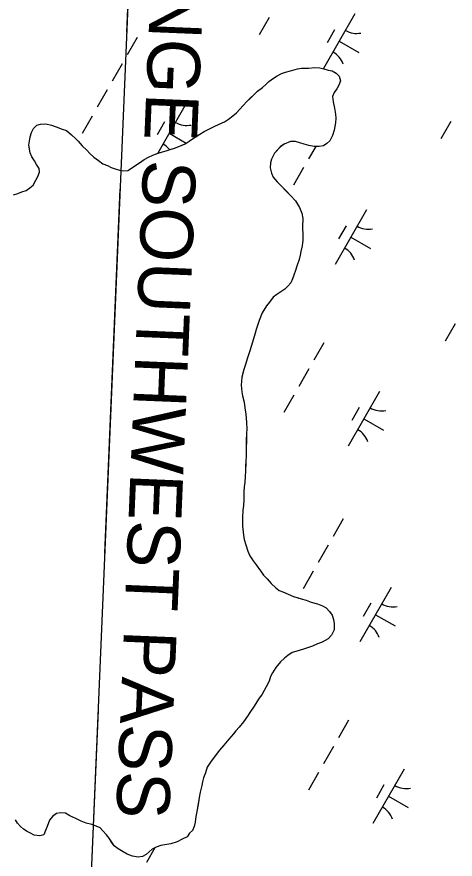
# Model space of a CAD drawing. Extents: x 3930721 to 3950824, y 220441 to 242861.
# Drawn here: x 3943622 to 3943971, y 232859 to 233530 of the extents above; entities that cross this region are included whole.
import ezdxf

# ---------------------------------------------------------------- set-up
doc = ezdxf.new("R2010")
doc.units = 0
for name, color, linetype in [('V-RIVR-RANG', 7, 'Continuous'), ('V-RIVR-RANG-IDEN', 7, 'Continuous'), ('V-TOPO-MINR', 7, 'Continuous'), ('V-TOPO-SHOR', 7, 'Continuous'), ('V-WETL-SWMP', 7, 'Continuous')]:
    doc.layers.add(name, color=color, linetype=linetype)

msp = doc.modelspace()

# ---------------------------------------------------------------- linework, layer by layer
at = {"layer": 'V-RIVR-RANG'}
for points in [[(3943765.57, 234844.6), (3943658.87, 232314.65)], [(3943765.57, 234844.6), (3943658.87, 232314.65)], [(3943721.82, 233807.23), (3943709.6, 233517.49)], [(3943704.33, 233392.6), (3943692.11, 233102.86)], [(3943686.84, 232977.97), (3943674.62, 232688.23)]]:
    msp.add_lwpolyline(points, dxfattribs=at)
at = {"layer": 'V-TOPO-MINR'}
msp.add_lwpolyline([(3943765.57, 234844.6), (3943658.87, 232314.65)], dxfattribs=at)
at = {"layer": 'V-TOPO-SHOR'}
for points in [[(3943631.81, 233427.64), (3943632.4, 233430.67), (3943633, 233434.26), (3943633.88, 233437.56), (3943635.58, 233440.86), (3943638.1, 233443.59), (3943641.15, 233444.38), (3943645.3, 233444.6), (3943649.98, 233443.43), (3943653.56, 233442.28), (3943658.24, 233440.28), (3943661.81, 233439.13), (3943665.64, 233435.76), (3943668.92, 233432.95), (3943671.1, 233430.71), (3943674.37, 233427.07), (3943677.92, 233423.71), (3943680.37, 233420.91), (3943683.65, 233418.1), (3943687.21, 233415.29), (3943690.77, 233412.76), (3943694.34, 233411.33), (3943697.36, 233409.9), (3943700.39, 233408.76), (3943703.96, 233407.61), (3943707.27, 233407.01), (3943710.6, 233407.52), (3943713.38, 233409.14), (3943716.18, 233411.04), (3943719.8, 233413.48), (3943723.43, 233416.19), (3943727.05, 233418.08), (3943730.39, 233419.7), (3943734.55, 233421.3), (3943738.16, 233422.36), (3943741.77, 233423.42), (3943745.1, 233424.48), (3943748.43, 233425.54), (3943752.33, 233427.15), (3943756.22, 233428.75), (3943759.28, 233430.65), (3943762.07, 233432.54), (3943764.86, 233434.44), (3943767.93, 233436.34), (3943771.27, 233438.5), (3943774.89, 233440.39), (3943779.34, 233442.54), (3943783.23, 233444.15), (3943787.41, 233446.03), (3943790.75, 233448.2), (3943794.1, 233450.92), (3943796.9, 233453.37), (3943799.7, 233456.1), (3943802.23, 233459.1), (3943805.31, 233462.38), (3943807.55, 233464.56), (3943810.91, 233467.83), (3943813.72, 233470.56), (3943817.62, 233473.55), (3943820.42, 233475.72), (3943822.66, 233478.18), (3943826.29, 233480.9), (3943829.36, 233482.79), (3943832.7, 233484.68), (3943836.03, 233485.74), (3943839.91, 233486.8), (3943845.46, 233488.38), (3943848.79, 233488.89), (3943854.31, 233488.82), (3943859.3, 233489.31), (3943863.16, 233488.98), (3943866.47, 233488.38), (3943869.77, 233487.23), (3943873.08, 233486.64), (3943876.38, 233484.93), (3943878.56, 233482.42), (3943879.61, 233478.81), (3943878.46, 233475.23), (3943876.77, 233472.49), (3943874.79, 233469.47), (3943873.37, 233466.17), (3943873.86, 233462.02), (3943874.9, 233457.03), (3943875.67, 233452.32), (3943875.9, 233449), (3943875.85, 233445.41), (3943874.67, 233439.62), (3943873.23, 233435.22), (3943871.24, 233431.1), (3943868.73, 233428.92), (3943866.21, 233427.02), (3943862.61, 233426.51), (3943858.74, 233426.56), (3943854.6, 233427.17), (3943850.75, 233428.33), (3943847.45, 233429.48), (3943843.86, 233430.36), (3943840, 233430.41), (3943834.99, 233428.26), (3943831.93, 233426.36), (3943827.16, 233421.18)], [(3943619.67, 233387.99), (3943623, 233389.05), (3943626.34, 233390.39), (3943629.67, 233391.45), (3943632.74, 233393.62), (3943635.25, 233395.8), (3943637.52, 233399.64), (3943638.94, 233402.66), (3943640.37, 233405.96), (3943640.13, 233409.01), (3943637.96, 233412.08), (3943636.34, 233415.14), (3943634.17, 233418.21), (3943632.83, 233421.54), (3943632.32, 233424.59), (3943631.81, 233427.64)], [(3943827.16, 233421.18), (3943824.88, 233416.51), (3943824.02, 233413.48), (3943823.69, 233409.61), (3943824.73, 233405.18), (3943826.08, 233402.12), (3943829.35, 233398.48), (3943833.71, 233394), (3943836.16, 233391.48), (3943839.98, 233387.56), (3943843.79, 233383.36), (3943847.04, 233378.07), (3943848.92, 233373.34), (3943849.69, 233369.18), (3943849.6, 233362.55), (3943849.78, 233355.36), (3943849.74, 233352.05), (3943849.12, 233347.36), (3943848.23, 233342.94), (3943847.64, 233339.91), (3943846.77, 233336.61), (3943845.04, 233331.38), (3943843.89, 233327.8), (3943842.46, 233324.22), (3943841.59, 233321.19), (3943840.16, 233317.9), (3943837.92, 233315.44), (3943835.4, 233312.98), (3943832.33, 233310.81), (3943828.98, 233308.65), (3943826.19, 233306.47), (3943823.1, 233302.64), (3943820.85, 233299.63), (3943817.46, 233294.15), (3943814.89, 233288.1), (3943812.58, 233280.95), (3943811.71, 233277.91), (3943809.68, 233270.75), (3943807.66, 233263.87), (3943805.65, 233258.37), (3943803.91, 233252.31), (3943802.76, 233249.01), (3943801.3, 233242.95), (3943800.66, 233236.6), (3943801.15, 233231.34), (3943801.65, 233228.01), (3943802.97, 233223.02), (3943803.74, 233218.59), (3943804.5, 233213.6), (3943804.97, 233206.96), (3943805.17, 233201.43), (3943804.85, 233198.39), (3943804.77, 233192.31), (3943804.71, 233187.61), (3943804.62, 233180.71), (3943804.28, 233175.74), (3943804.23, 233172.69), (3943804.17, 233167.72), (3943803.85, 233164.4), (3943803.5, 233158.88), (3943803.18, 233155.84), (3943802.85, 233151.43), (3943802.77, 233145.35), (3943802.43, 233140.93), (3943802.1, 233137.06), (3943801.75, 233131.26), (3943801.66, 233124.35), (3943802.67, 233117.15), (3943803.18, 233113.83), (3943804.5, 233109.39), (3943806.1, 233104.39), (3943807.71, 233100.78), (3943810.14, 233096.87), (3943812.58, 233093.52), (3943816.12, 233088.78), (3943818.56, 233085.43), (3943821.28, 233082.35), (3943824.55, 233078.71), (3943828.38, 233075.35), (3943830.83, 233073.1), (3943833.86, 233072.23), (3943837.98, 233070.24), (3943842.38, 233068.53), (3943848.44, 233066.51), (3943852.29, 233065.35), (3943856.42, 233063.92), (3943861.38, 233062.47), (3943865.5, 233061.03), (3943868.25, 233059.34), (3943870.97, 233056.54), (3943873.14, 233053.47), (3943874.21, 233050.14), (3943874.71, 233046.54), (3943874.65, 233041.84), (3943872.66, 233037.72), (3943869.85, 233034.71), (3943865.12, 233032.01), (3943861.51, 233030.68), (3943857.34, 233028.8), (3943851.78, 233026.94), (3943845.96, 233025.08)], [(3943845.96, 233025.08), (3943841.24, 233023.76), (3943837.89, 233021.32), (3943835.1, 233019.42), (3943832.02, 233016.42), (3943828.36, 233011.77), (3943825.54, 233007.66), (3943824.12, 233004.64), (3943822.97, 233001.06), (3943820.7, 232996.39), (3943817.3, 232990.63), (3943814.49, 232986.8), (3943811.09, 232981.04), (3943807.71, 232976.1), (3943805.74, 232973.09), (3943802.64, 232968.71), (3943798.98, 232964.33), (3943796.46, 232961.6), (3943794.49, 232959.14), (3943790.84, 232954.77), (3943786.91, 232950.12), (3943783.54, 232946.02), (3943779.89, 232941.65), (3943776.23, 232936.44), (3943773.69, 232932.61), (3943772.25, 232928.2), (3943770.81, 232924.07), (3943769.94, 232921.04), (3943769.35, 232918.01), (3943768.17, 232912.77), (3943767.28, 232908.36), (3943766.38, 232902.85), (3943765.48, 232897.33), (3943764.59, 232893.2), (3943763.98, 232888.78), (3943763.39, 232885.47), (3943761.96, 232882.17), (3943759.72, 232879.99), (3943757.75, 232877.25), (3943753.85, 232875.37), (3943749.68, 232873.21), (3943744.68, 232871.62), (3943741.63, 232871.11), (3943736.92, 232870.34), (3943733.04, 232869.01), (3943729.98, 232867.39), (3943727.46, 232865.21), (3943725.22, 232863.03), (3943722.16, 232861.41), (3943718.83, 232860.91), (3943714.14, 232861.8), (3943710.02, 232863.23), (3943706.72, 232865.21), (3943702.88, 232867.48), (3943699.6, 232870.01), (3943697.71, 232872.8), (3943695.81, 232876.14), (3943693.64, 232878.66), (3943690.64, 232882.01), (3943688.46, 232884.25), (3943685.44, 232885.67), (3943681.86, 232886.83), (3943677.45, 232887.99), (3943673.33, 232889.71), (3943669.21, 232891.7), (3943664.54, 232893.97), (3943660.97, 232895.95), (3943657.38, 232896.27), (3943653.78, 232895.77), (3943650.71, 232893.32), (3943648.18, 232890.32), (3943646.45, 232885.36), (3943645.03, 232882.06), (3943643.88, 232878.76), (3943640.55, 232877.98), (3943636.14, 232878.59), (3943633.12, 232880.01), (3943630.37, 232881.43), (3943627.63, 232883.12), (3943625.17, 232885.37), (3943622.71, 232887.89), (3943621.09, 232890.68)]]:
    msp.add_lwpolyline(points, dxfattribs=at)
at = {"layer": 'V-WETL-SWMP'}
for p, q in [((3943823.01, 233529.13), (3943815.06, 233515.25)), ((3943891.13, 233531.94), (3943866.29, 233488.56)), ((3943875, 233519.29), (3943869.03, 233508.88)), ((3943717.97, 233513.23), (3943710.02, 233499.35)), ((3943878.71, 233510.25), (3943894.33, 233501.3)), ((3943706.04, 233492.41), (3943698.09, 233478.52)), ((3943845.46, 233488.38), (3943848.79, 233488.89)), ((3943848.79, 233488.89), (3943854.32, 233488.82)), ((3943854.32, 233488.82), (3943859.3, 233489.31)), ((3943859.3, 233489.31), (3943863.16, 233488.98)), ((3943863.16, 233488.98), (3943866.47, 233488.38)), ((3943826.29, 233480.9), (3943829.36, 233482.79)), ((3943829.36, 233482.79), (3943832.7, 233484.68)), ((3943832.7, 233484.68), (3943836.03, 233485.74)), ((3943836.03, 233485.74), (3943839.91, 233486.8)), ((3943839.91, 233486.8), (3943845.46, 233488.38)), ((3943866.47, 233488.38), (3943869.77, 233487.23)), ((3943869.77, 233487.23), (3943873.08, 233486.63)), ((3943873.08, 233486.63), (3943876.38, 233484.93)), ((3943876.38, 233484.93), (3943878.56, 233482.42)), ((3943878.56, 233482.42), (3943879.61, 233478.81)), ((3943817.62, 233473.55), (3943820.42, 233475.72)), ((3943820.42, 233475.72), (3943822.66, 233478.18)), ((3943822.66, 233478.18), (3943826.29, 233480.9)), ((3943878.46, 233475.23), (3943876.77, 233472.49)), ((3943879.61, 233478.81), (3943878.46, 233475.23)), ((3943694.12, 233471.58), (3943686.16, 233457.7)), ((3943805.31, 233462.38), (3943813.71, 233470.56)), ((3943813.71, 233470.56), (3943817.62, 233473.55)), ((3943874.79, 233469.47), (3943873.37, 233466.17)), ((3943876.77, 233472.49), (3943874.79, 233469.47)), ((3943802.23, 233459.1), (3943805.31, 233462.38)), ((3943873.37, 233466.17), (3943873.86, 233462.02)), ((3943873.86, 233462.02), (3943874.9, 233457.03)), ((3943755.94, 233458.73), (3943734.49, 233421.27)), ((3943796.9, 233453.37), (3943799.7, 233456.09)), ((3943799.7, 233456.09), (3943802.23, 233459.1)), ((3943874.9, 233457.03), (3943875.67, 233452.32)), ((3943682.19, 233450.75), (3943674.24, 233436.87)), ((3943790.75, 233448.2), (3943794.1, 233450.92)), ((3943794.1, 233450.92), (3943796.9, 233453.37)), ((3943875.67, 233452.32), (3943875.9, 233449)), ((3943875.9, 233449), (3943875.85, 233445.41)), ((3943635.58, 233440.86), (3943638.1, 233443.59)), ((3943638.1, 233443.59), (3943641.15, 233444.38)), ((3943641.15, 233444.38), (3943645.3, 233444.6)), ((3943645.3, 233444.6), (3943649.98, 233443.43)), ((3943649.98, 233443.43), (3943653.56, 233442.28)), ((3943653.56, 233442.28), (3943658.24, 233440.28)), ((3943739.8, 233446.08), (3943733.84, 233435.67)), ((3943774.89, 233440.39), (3943779.34, 233442.54)), ((3943779.34, 233442.54), (3943783.23, 233444.15)), ((3943783.23, 233444.15), (3943787.41, 233446.03)), ((3943787.41, 233446.03), (3943790.75, 233448.2)), ((3943875.85, 233445.41), (3943874.67, 233439.62)), ((3943967.35, 233446.46), (3943959.4, 233432.58)), ((3943633, 233434.26), (3943633.87, 233437.56)), ((3943633.87, 233437.56), (3943635.58, 233440.86)), ((3943658.24, 233440.28), (3943661.81, 233439.13)), ((3943661.81, 233439.13), (3943665.64, 233435.76)), ((3943665.64, 233435.76), (3943668.92, 233432.95)), ((3943743.52, 233437.04), (3943757.07, 233429.28)), ((3943764.86, 233434.44), (3943767.93, 233436.34)), ((3943767.93, 233436.34), (3943771.27, 233438.5)), ((3943771.27, 233438.5), (3943774.89, 233440.39)), ((3943873.23, 233435.22), (3943871.24, 233431.1)), ((3943874.67, 233439.62), (3943873.23, 233435.22)), ((3943631.81, 233427.64), (3943632.4, 233430.67)), ((3943632.4, 233430.67), (3943633, 233434.26)), ((3943668.92, 233432.95), (3943671.1, 233430.71)), ((3943671.1, 233430.71), (3943674.37, 233427.07)), ((3943748.43, 233425.54), (3943756.22, 233428.75)), ((3943756.22, 233428.75), (3943759.28, 233430.65)), ((3943759.28, 233430.65), (3943764.86, 233434.44)), ((3943834.99, 233428.26), (3943831.93, 233426.37)), ((3943840, 233430.4), (3943834.99, 233428.26)), ((3943843.87, 233430.35), (3943840, 233430.4)), ((3943847.45, 233429.48), (3943843.87, 233430.35)), ((3943850.75, 233428.33), (3943847.45, 233429.48)), ((3943854.6, 233427.17), (3943850.75, 233428.33)), ((3943868.73, 233428.92), (3943866.21, 233427.02)), ((3943871.24, 233431.1), (3943868.73, 233428.92)), ((3943632.83, 233421.54), (3943631.81, 233427.64)), ((3943634.17, 233418.21), (3943632.83, 233421.54)), ((3943674.37, 233427.07), (3943677.92, 233423.71)), ((3943677.92, 233423.71), (3943680.37, 233420.91)), ((3943734.56, 233421.3), (3943741.77, 233423.41)), ((3943741.77, 233423.41), (3943748.43, 233425.54)), ((3943831.93, 233426.37), (3943827.16, 233421.18)), ((3943860.01, 233426.55), (3943854.36, 233416.68)), ((3943858.74, 233426.56), (3943854.6, 233427.17)), ((3943862.61, 233426.51), (3943858.74, 233426.56)), ((3943866.21, 233427.02), (3943862.61, 233426.51)), ((3943636.34, 233415.14), (3943634.17, 233418.21)), ((3943637.96, 233412.08), (3943636.34, 233415.14)), ((3943680.37, 233420.91), (3943683.65, 233418.1)), ((3943683.65, 233418.1), (3943687.21, 233415.29)), ((3943687.21, 233415.29), (3943690.77, 233412.76)), ((3943719.8, 233413.48), (3943723.43, 233416.19)), ((3943723.43, 233416.19), (3943727.05, 233418.08)), ((3943727.05, 233418.08), (3943730.39, 233419.7)), ((3943730.39, 233419.7), (3943734.56, 233421.3)), ((3943824.88, 233416.51), (3943824.02, 233413.48)), ((3943827.16, 233421.18), (3943824.88, 233416.51)), ((3943640.13, 233409.01), (3943637.96, 233412.08)), ((3943640.37, 233405.96), (3943640.13, 233409.01)), ((3943690.77, 233412.76), (3943694.34, 233411.33)), ((3943694.34, 233411.33), (3943697.36, 233409.91)), ((3943697.36, 233409.91), (3943700.39, 233408.76)), ((3943700.39, 233408.76), (3943703.97, 233407.61)), ((3943710.6, 233407.52), (3943713.39, 233409.14)), ((3943713.39, 233409.14), (3943716.18, 233411.04)), ((3943716.18, 233411.04), (3943719.8, 233413.48)), ((3943824.02, 233413.48), (3943823.69, 233409.61)), ((3943823.69, 233409.61), (3943824.73, 233405.18)), ((3943850.38, 233409.74), (3943842.43, 233395.86)), ((3943637.52, 233399.64), (3943638.94, 233402.66)), ((3943638.94, 233402.66), (3943640.37, 233405.96)), ((3943703.97, 233407.61), (3943707.27, 233407.01)), ((3943707.27, 233407.01), (3943710.6, 233407.52)), ((3943824.73, 233405.18), (3943826.08, 233402.12)), ((3943826.08, 233402.12), (3943829.35, 233398.48)), ((3943632.74, 233393.62), (3943635.25, 233395.8)), ((3943635.25, 233395.8), (3943637.52, 233399.64)), ((3943829.35, 233398.48), (3943839.98, 233387.56)), ((3943619.67, 233387.99), (3943623, 233389.05)), ((3943623, 233389.05), (3943626.34, 233390.39)), ((3943626.34, 233390.39), (3943629.67, 233391.45)), ((3943629.67, 233391.45), (3943632.74, 233393.62)), ((3943839.98, 233387.56), (3943843.79, 233383.36)), ((3943843.79, 233383.36), (3943847.04, 233378.07)), ((3943847.04, 233378.07), (3943848.91, 233373.34)), ((3943900.28, 233376.07), (3943875.43, 233332.68)), ((3943848.91, 233373.34), (3943849.69, 233369.19)), ((3943849.69, 233369.19), (3943849.6, 233362.55)), ((3943849.6, 233362.55), (3943849.78, 233355.36)), ((3943884.15, 233363.41), (3943878.18, 233353)), ((3943849.78, 233355.36), (3943849.74, 233352.05)), ((3943849.74, 233352.05), (3943849.12, 233347.36)), ((3943887.86, 233354.37), (3943903.48, 233345.43)), ((3943848.23, 233342.94), (3943847.64, 233339.91)), ((3943849.12, 233347.36), (3943848.23, 233342.94)), ((3943846.77, 233336.61), (3943845.04, 233331.38)), ((3943847.64, 233339.91), (3943846.77, 233336.61)), ((3943843.89, 233327.8), (3943842.46, 233324.22)), ((3943845.04, 233331.38), (3943843.89, 233327.8)), ((3943841.59, 233321.19), (3943840.16, 233317.9)), ((3943842.46, 233324.22), (3943841.59, 233321.19)), ((3943837.92, 233315.44), (3943835.4, 233312.98)), ((3943840.16, 233317.9), (3943837.92, 233315.44)), ((3943828.98, 233308.65), (3943826.19, 233306.47)), ((3943832.33, 233310.81), (3943828.98, 233308.65)), ((3943835.4, 233312.98), (3943832.33, 233310.81)), ((3943823.1, 233302.64), (3943820.85, 233299.63)), ((3943826.19, 233306.47), (3943823.1, 233302.64)), ((3943817.46, 233294.15), (3943814.89, 233288.1)), ((3943820.85, 233299.63), (3943817.46, 233294.15)), ((3943814.89, 233288.1), (3943812.58, 233280.94)), ((3943812.58, 233280.94), (3943811.71, 233277.91)), ((3943970.87, 233285.42), (3943962.92, 233271.54)), ((3943811.71, 233277.91), (3943809.68, 233270.75)), ((3943809.68, 233270.75), (3943807.66, 233263.87)), ((3943866.49, 233270.35), (3943858.54, 233256.46)), ((3943807.66, 233263.87), (3943805.65, 233258.37)), ((3943805.65, 233258.37), (3943803.91, 233252.31)), ((3943802.76, 233249.01), (3943801.3, 233242.95)), ((3943803.91, 233252.31), (3943802.76, 233249.01)), ((3943854.56, 233249.52), (3943846.61, 233235.64)), ((3943801.3, 233242.95), (3943800.66, 233236.6)), ((3943800.66, 233236.6), (3943801.14, 233231.34)), ((3943801.14, 233231.34), (3943801.65, 233228.01)), ((3943801.65, 233228.01), (3943802.97, 233223.02)), ((3943842.64, 233228.7), (3943834.68, 233214.81)), ((3943910.76, 233231.51), (3943885.91, 233188.12)), ((3943802.97, 233223.02), (3943803.74, 233218.59)), ((3943803.74, 233218.59), (3943804.5, 233213.6)), ((3943894.62, 233218.86), (3943888.66, 233208.44)), ((3943804.5, 233213.6), (3943804.97, 233206.96)), ((3943804.97, 233206.96), (3943805.17, 233201.43)), ((3943898.33, 233209.81), (3943913.95, 233200.87)), ((3943805.17, 233201.43), (3943804.85, 233198.39)), ((3943804.85, 233198.39), (3943804.62, 233180.71)), ((3943804.62, 233180.71), (3943804.28, 233175.73)), ((3943804.28, 233175.73), (3943804.17, 233167.72)), ((3943804.17, 233167.72), (3943803.85, 233164.41)), ((3943803.85, 233164.41), (3943803.5, 233158.88)), ((3943803.18, 233155.84), (3943802.85, 233151.43)), ((3943803.5, 233158.88), (3943803.18, 233155.84)), ((3943802.85, 233151.43), (3943802.77, 233145.35)), ((3943802.43, 233140.93), (3943802.1, 233137.06)), ((3943802.77, 233145.35), (3943802.43, 233140.93)), ((3943802.1, 233137.06), (3943801.75, 233131.26)), ((3943801.75, 233131.26), (3943801.66, 233124.35)), ((3943881.93, 233130.13), (3943873.98, 233116.25)), ((3943801.66, 233124.35), (3943802.67, 233117.15)), ((3943802.67, 233117.15), (3943803.18, 233113.83)), ((3943803.18, 233113.83), (3943804.5, 233109.39)), ((3943804.5, 233109.39), (3943806.1, 233104.39)), ((3943870.01, 233109.3), (3943862.06, 233095.42)), ((3943806.1, 233104.39), (3943807.71, 233100.78)), ((3943807.71, 233100.78), (3943810.14, 233096.87)), ((3943810.14, 233096.87), (3943812.58, 233093.52)), ((3943812.58, 233093.52), (3943816.12, 233088.78)), ((3943816.12, 233088.78), (3943818.56, 233085.43)), ((3943858.08, 233088.48), (3943850.13, 233074.59)), ((3943818.56, 233085.43), (3943821.28, 233082.35)), ((3943821.28, 233082.35), (3943824.55, 233078.71)), ((3943824.55, 233078.71), (3943828.38, 233075.35)), ((3943828.38, 233075.35), (3943830.83, 233073.1)), ((3943830.83, 233073.1), (3943833.86, 233072.23)), ((3943919.91, 233075.63), (3943895.06, 233032.24)), ((3943833.86, 233072.23), (3943837.98, 233070.24)), ((3943837.98, 233070.24), (3943842.38, 233068.53)), ((3943842.38, 233068.53), (3943848.44, 233066.51)), ((3943846.15, 233067.65), (3943845.97, 233067.33)), ((3943848.44, 233066.51), (3943852.29, 233065.35)), ((3943852.29, 233065.35), (3943856.42, 233063.92)), ((3943856.42, 233063.92), (3943861.38, 233062.47)), ((3943861.38, 233062.47), (3943865.5, 233061.03)), ((3943865.5, 233061.03), (3943868.25, 233059.34)), ((3943903.77, 233062.98), (3943897.8, 233052.56)), ((3943868.25, 233059.34), (3943870.97, 233056.54)), ((3943870.97, 233056.54), (3943873.15, 233053.47)), ((3943873.15, 233053.47), (3943874.21, 233050.14)), ((3943907.48, 233053.94), (3943923.1, 233044.99)), ((3943874.21, 233050.14), (3943874.71, 233046.54)), ((3943874.71, 233046.54), (3943874.65, 233041.84)), ((3943874.65, 233041.84), (3943872.66, 233037.72)), ((3943869.86, 233034.71), (3943865.12, 233032.01)), ((3943872.66, 233037.72), (3943869.86, 233034.71)), ((3943851.78, 233026.94), (3943845.96, 233025.08)), ((3943857.34, 233028.8), (3943851.78, 233026.94)), ((3943861.51, 233030.68), (3943857.34, 233028.8)), ((3943865.12, 233032.01), (3943861.51, 233030.68)), ((3943835.1, 233019.42), (3943832.02, 233016.42)), ((3943837.89, 233021.32), (3943835.1, 233019.42)), ((3943841.24, 233023.76), (3943837.89, 233021.32)), ((3943845.96, 233025.08), (3943841.24, 233023.76)), ((3943832.02, 233016.42), (3943828.36, 233011.77)), ((3943825.54, 233007.66), (3943824.12, 233004.64)), ((3943828.36, 233011.77), (3943825.54, 233007.66)), ((3943822.97, 233001.06), (3943820.7, 232996.39)), ((3943824.12, 233004.64), (3943822.97, 233001.06)), ((3943820.7, 232996.39), (3943817.3, 232990.63)), ((3943814.49, 232986.8), (3943811.09, 232981.04)), ((3943817.3, 232990.63), (3943814.49, 232986.8)), ((3943811.09, 232981.04), (3943807.71, 232976.1)), ((3943805.74, 232973.09), (3943802.64, 232968.71)), ((3943807.71, 232976.1), (3943805.74, 232973.09)), ((3943802.64, 232968.71), (3943798.98, 232964.33)), ((3943886.11, 232969.91), (3943878.16, 232956.03)), ((3943794.49, 232959.14), (3943790.84, 232954.77)), ((3943796.46, 232961.6), (3943794.49, 232959.14)), ((3943798.98, 232964.33), (3943796.46, 232961.6)), ((3943790.84, 232954.77), (3943786.91, 232950.12)), ((3943783.54, 232946.02), (3943779.89, 232941.64)), ((3943786.91, 232950.12), (3943783.54, 232946.02)), ((3943874.19, 232949.09), (3943866.23, 232935.2)), ((3943779.89, 232941.64), (3943776.23, 232936.44)), ((3943773.69, 232932.6), (3943772.25, 232928.2)), ((3943776.23, 232936.44), (3943773.69, 232932.6)), ((3943772.25, 232928.2), (3943770.81, 232924.07)), ((3943862.26, 232928.26), (3943854.31, 232914.38)), ((3943930.38, 232931.07), (3943905.53, 232887.69)), ((3943769.94, 232921.04), (3943769.35, 232918.01)), ((3943770.81, 232924.07), (3943769.94, 232921.04)), ((3943768.17, 232912.77), (3943767.28, 232908.36)), ((3943769.35, 232918.01), (3943768.17, 232912.77)), ((3943914.24, 232918.42), (3943908.28, 232908.01)), ((3943767.28, 232908.36), (3943765.48, 232897.33)), ((3943917.96, 232909.38), (3943933.58, 232900.43)), ((3943650.71, 232893.32), (3943648.18, 232890.32)), ((3943653.78, 232895.77), (3943650.71, 232893.32)), ((3943657.38, 232896.27), (3943653.78, 232895.77)), ((3943660.97, 232895.95), (3943657.38, 232896.27)), ((3943664.54, 232893.97), (3943660.97, 232895.95)), ((3943669.21, 232891.7), (3943664.54, 232893.97)), ((3943764.59, 232893.2), (3943763.98, 232888.78)), ((3943765.48, 232897.33), (3943764.59, 232893.2)), ((3943622.71, 232887.89), (3943621.09, 232890.67)), ((3943625.17, 232885.37), (3943622.71, 232887.89)), ((3943627.63, 232883.12), (3943625.17, 232885.37)), ((3943646.45, 232885.36), (3943645.03, 232882.06)), ((3943648.18, 232890.32), (3943646.45, 232885.36)), ((3943673.33, 232889.71), (3943669.21, 232891.7)), ((3943677.45, 232887.99), (3943673.33, 232889.71)), ((3943681.86, 232886.83), (3943677.45, 232887.99)), ((3943685.44, 232885.67), (3943681.86, 232886.83)), ((3943688.46, 232884.25), (3943685.44, 232885.67)), ((3943763.39, 232885.47), (3943761.96, 232882.17)), ((3943763.98, 232888.78), (3943763.39, 232885.47)), ((3943630.37, 232881.43), (3943627.63, 232883.12)), ((3943633.12, 232880.01), (3943630.37, 232881.43)), ((3943636.14, 232878.59), (3943633.12, 232880.01)), ((3943640.55, 232877.98), (3943636.14, 232878.59)), ((3943643.88, 232878.76), (3943640.55, 232877.98)), ((3943645.03, 232882.06), (3943643.88, 232878.76)), ((3943690.64, 232882.01), (3943688.46, 232884.25)), ((3943693.64, 232878.66), (3943690.64, 232882.01)), ((3943695.81, 232876.14), (3943693.64, 232878.66)), ((3943759.72, 232879.99), (3943757.75, 232877.25)), ((3943761.96, 232882.17), (3943759.72, 232879.99)), ((3943697.7, 232872.8), (3943695.81, 232876.14)), ((3943699.6, 232870.01), (3943697.7, 232872.8)), ((3943749.68, 232873.21), (3943744.68, 232871.62)), ((3943753.85, 232875.37), (3943749.68, 232873.21)), ((3943757.75, 232877.25), (3943753.85, 232875.37)), ((3943702.89, 232867.48), (3943699.6, 232870.01)), ((3943706.73, 232865.21), (3943702.89, 232867.48)), ((3943710.02, 232863.23), (3943706.73, 232865.21)), ((3943727.46, 232865.21), (3943725.22, 232863.03)), ((3943732.11, 232868.52), (3943725.41, 232856.83)), ((3943729.97, 232867.39), (3943727.46, 232865.21)), ((3943733.04, 232869.01), (3943729.97, 232867.39)), ((3943736.92, 232870.34), (3943733.04, 232869.01)), ((3943741.63, 232871.11), (3943736.92, 232870.34)), ((3943744.68, 232871.62), (3943741.63, 232871.11)), ((3943714.14, 232861.8), (3943710.02, 232863.23)), ((3943718.83, 232860.91), (3943714.14, 232861.8)), ((3943722.16, 232861.41), (3943718.83, 232860.91)), ((3943725.22, 232863.03), (3943722.16, 232861.41))]:
    msp.add_line(p, q, dxfattribs=at)
for centre, start, end in [((3943892.64, 233534.1), 239.42788, 280.97154), ((3943865.19, 233486.16), 19.42788, 60.97154), ((3943757.45, 233460.89), 239.42788, 280.97154), ((3943730, 233412.95), 38.95222, 60.97154), ((3943901.79, 233378.22), 239.42788, 280.97154), ((3943874.34, 233330.28), 19.42788, 60.97154), ((3943912.27, 233233.67), 239.42788, 280.97154), ((3943884.81, 233185.73), 19.42788, 60.97154), ((3943921.41, 233077.79), 239.42788, 280.97154), ((3943893.96, 233029.85), 19.42788, 60.97154), ((3943931.89, 232933.23), 239.42788, 280.97154), ((3943904.43, 232885.29), 19.42788, 60.97154)]:
    msp.add_arc(centre, 17.62, start, end, dxfattribs=at)

# ---------------------------------------------------------------- texts
at = {"layer": 'V-RIVR-RANG-IDEN'}
msp.add_text('ENTRANCE RANGE SOUTHWEST PASS', height=42, rotation=267.62762, dxfattribs=at).set_placement((3943745.32, 233955.76))

doc.saveas('drawing.dxf')
